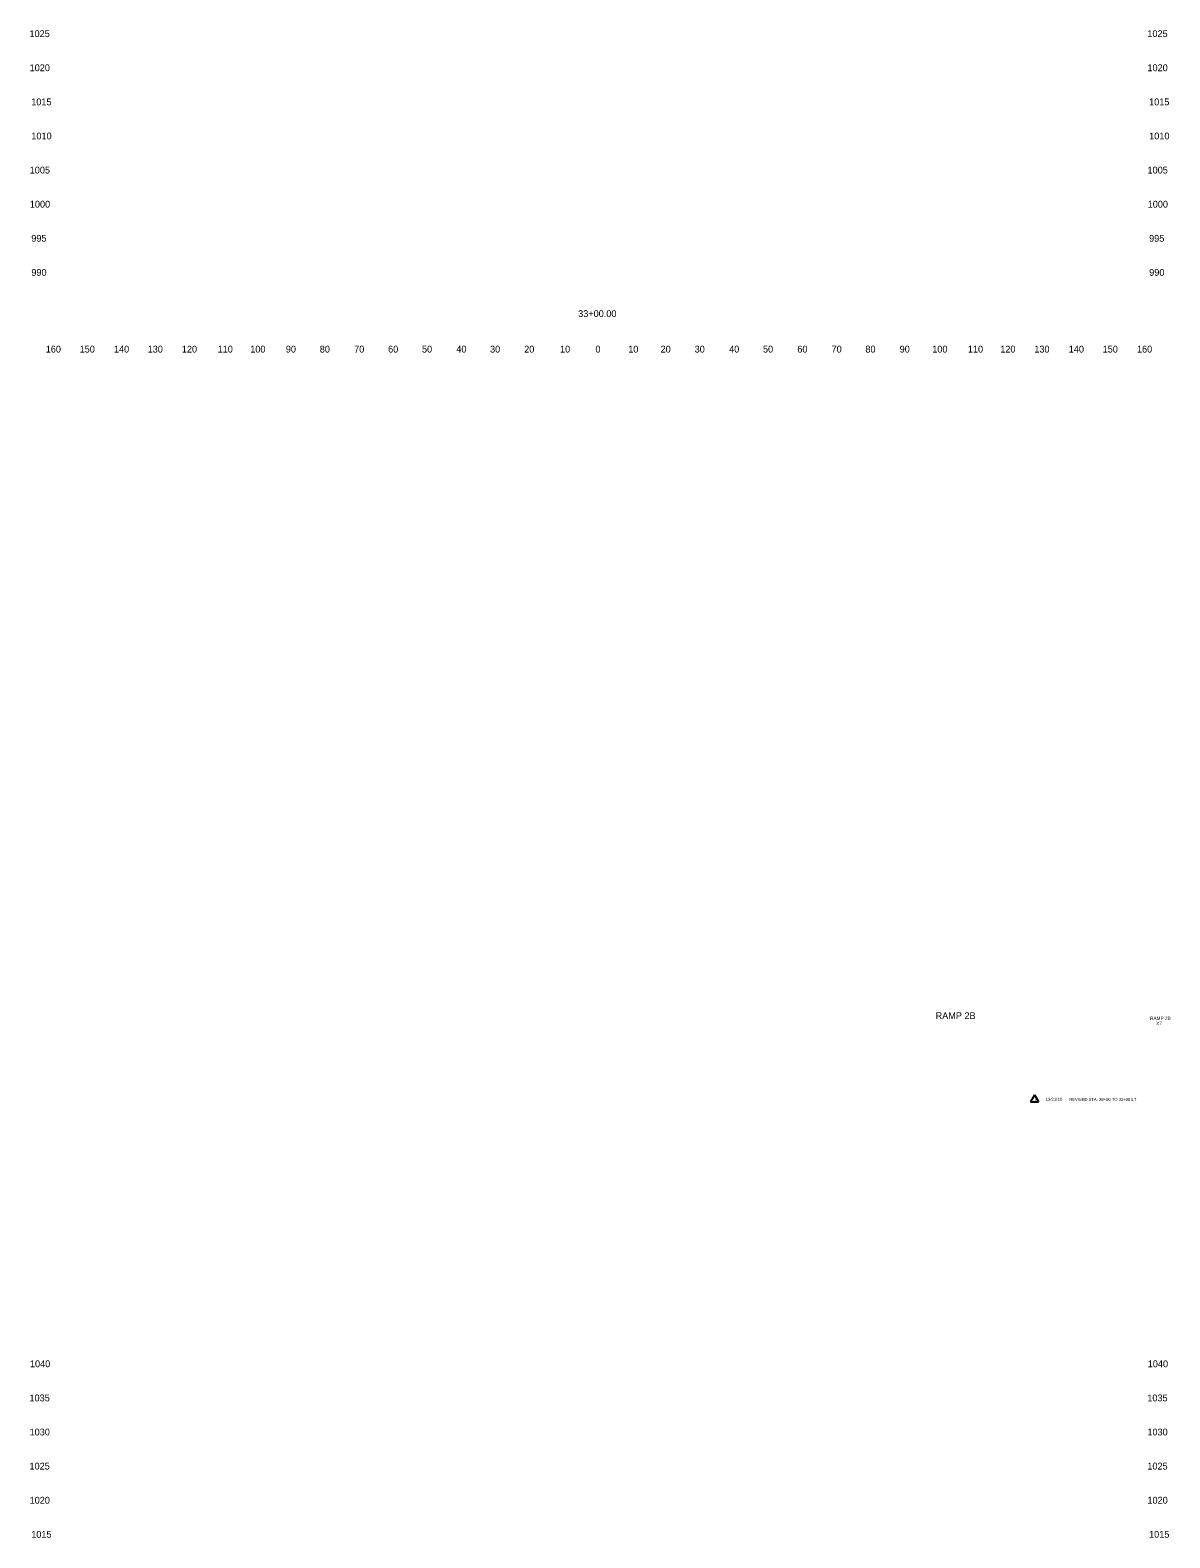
# Model space of a CAD drawing. Extents: x 4994 to 6358, y 4997 to 8804.
# Drawn here: x 4993.5 to 5327.7, y 7450 to 7892 of the extents above; entities that cross this region are included whole.
import ezdxf

# ---------------------------------------------------------------- set-up
doc = ezdxf.new("R2010")
doc.units = 0
for name, color, linetype in [('RD_SHT_ID', 7, 'Continuous'), ('RD_SHT_TX', 7, 'Continuous'), ('RD_XS_TX_Offset', 7, 'Continuous'), ('RD_XS_TX_Station', 7, 'Continuous')]:
    doc.layers.add(name, color=color, linetype=linetype)

msp = doc.modelspace()

# ---------------------------------------------------------------- linework, layer by layer
at = {"layer": 'RD_SHT_TX'}
for p, q in [((5288.05, 7579.83), (5286.91, 7577.8)), ((5286.91, 7577.8), (5289.19, 7577.8)), ((5288.05, 7579.83), (5289.19, 7577.8))]:
    msp.add_line(p, q, dxfattribs=at)

# ---------------------------------------------------------------- texts
at = {"layer": 'RD_SHT_ID'}
for s, height, p in [('RAMP 2B', 2, (5259.05, 7602.06)), ('RAMP 2B', 1, (5321.94, 7601.8)), ('X7', 1, (5323.74, 7600.3))]:
    msp.add_text(s, height=height, dxfattribs=at).set_placement(p)
at = {"layer": 'RD_SHT_TX'}
for s, p in [('1', (5288.05, 7578.13)), ('12/21/18', (5291.35, 7578.12)), ('REVISED STA. 28+00 TO 33+00 LT', (5298.25, 7578.09))]:
    msp.add_text(s, height=0.88, dxfattribs=at).set_placement(p)
at = {"layer": 'RD_XS_TX_Offset'}
for s, p in [('1025', (4993.34, 7890)), ('1025', (5321.14, 7890)), ('1020', (4993.37, 7880)), ('1020', (5321.17, 7880)), ('1015', (4993.85, 7870)), ('1015', (5321.65, 7870)), ('1010', (4993.88, 7860)), ('1010', (5321.68, 7860)), ('1005', (4993.4, 7850)), ('1005', (5321.2, 7850)), ('1000', (4993.44, 7840)), ('1000', (5321.24, 7840)), ('995', (4993.86, 7830)), ('995', (5321.66, 7830)), ('990', (4993.89, 7820)), ('990', (5321.69, 7820)), ('160', (4998.1, 7797.5)), ('150', (5008.04, 7797.5)), ('140', (5018.1, 7797.5)), ('130', (5027.99, 7797.5)), ('120', (5038.01, 7797.5)), ('110', (5048.51, 7797.5)), ('100', (5058.07, 7797.5)), ('90', (5068.5, 7797.5)), ('80', (5078.46, 7797.5)), ('70', (5088.54, 7797.5)), ('60', (5098.5, 7797.5)), ('50', (5108.43, 7797.5)), ('40', (5118.5, 7797.5)), ('30', (5128.39, 7797.5)), ('20', (5138.4, 7797.5)), ('10', (5148.91, 7797.5)), ('0', (5159.3, 7797.5)), ('0', (5159.3, 7797.5)), ('10', (5168.91, 7797.5)), ('20', (5178.4, 7797.5)), ('30', (5188.39, 7797.5)), ('40', (5198.5, 7797.5)), ('50', (5208.43, 7797.5)), ('60', (5218.5, 7797.5)), ('70', (5228.54, 7797.5)), ('80', (5238.46, 7797.5)), ('90', (5248.5, 7797.5)), ('100', (5258.07, 7797.5)), ('110', (5268.51, 7797.5)), ('120', (5278.01, 7797.5)), ('130', (5287.99, 7797.5)), ('140', (5298.1, 7797.5)), ('150', (5308.04, 7797.5)), ('160', (5318.1, 7797.5)), ('1040', (4993.47, 7500)), ('1040', (5321.27, 7500)), ('1035', (4993.33, 7490)), ('1035', (5321.13, 7490)), ('1030', (4993.36, 7480)), ('1030', (5321.16, 7480)), ('1025', (4993.34, 7470)), ('1025', (5321.14, 7470)), ('1020', (4993.37, 7460)), ('1020', (5321.17, 7460)), ('1015', (4993.85, 7450)), ('1015', (5321.65, 7450))]:
    msp.add_text(s, height=2, dxfattribs=at).set_placement(p)
at = {"layer": 'RD_XS_TX_Station'}
msp.add_text('33+00.00', height=2, dxfattribs=at).set_placement((5154.23, 7807.92))

doc.saveas('drawing.dxf')
